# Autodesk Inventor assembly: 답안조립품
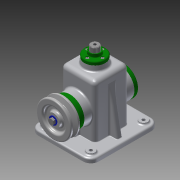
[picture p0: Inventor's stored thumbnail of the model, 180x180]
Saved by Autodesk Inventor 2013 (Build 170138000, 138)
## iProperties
Created: 2016-01
Part Number: 답안조립품
Document SubType Name: Assembly
Designer: User
Author: User
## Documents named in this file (19)
- C:\Users\User\Desktop\460126V1011\답안조립품.iam
- C:\Users\User\Desktop\460126V1011\본체.ipt
- C:\Users\User\Desktop\460126V1011\뒤커버.ipt
- C:\Users\User\Desktop\460126V1011\상부부시.ipt
- C:\Users\User\Desktop\460126V1011\앞커버.ipt
- C:\Users\User\Desktop\460126V1011\볼트 M4 x 10.ipt
- C:\Users\User\Desktop\460126V1011\볼트 M3 x 8.ipt
- C:\Users\User\Desktop\460126V1011\편심축.ipt
- C:\Users\User\Desktop\460126V1011\키 5 x 5 x 14.ipt
- C:\Users\User\Desktop\460126V1011\베어링 15 x 35 x 11.ipt
- C:\Users\User\Desktop\460126V1011\멈춤링 15 x 1.ipt
- C:\Users\User\Desktop\460126V1011\링크.ipt
- C:\Users\User\Desktop\460126V1011\멈춤링 6 x 5.ipt
- C:\Users\User\Desktop\460126V1011\슬라이드바.ipt
- C:\Users\User\Desktop\460126V1011\고정핀.ipt
- C:\Users\User\Desktop\460126V1011\오일실 15 25 7.ipt
- C:\Users\User\Desktop\460126V1011\V-벨트풀리.ipt
- C:\Users\User\Desktop\460126V1011\볼트 M6 x 12.ipt
- C:\Users\User\Desktop\460126V1011\와셔.ipt
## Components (15 placed, 5 different names)
1. 고정핀:1
2. V-벨트풀리:1 — 각도:2
3. ISO 4018 M6 x 12:1 — 각도:3
4. ISO 4762 M4 x 10:2
5. ISO 4762 M4 x 10:3
6. ISO 4762 M4 x 10:4
7. ISO 4762 M4 x 10:5
8. ISO 4762 M3 x 8:1
9. ISO 4762 M3 x 8:2
10. ISO 4762 M3 x 8:3
11. ISO 4762 M3 x 8:4
12. ISO 4762 M4 x 10:1
13. ISO 4762 M4 x 10:6
14. ISO 4762 M4 x 10:7
15. ISO 4762 M4 x 10:8
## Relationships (2: Angle 2)
- 각도:2 [Angle]: V-벨트풀리:1
- 각도:3 [Angle]: ISO 4018 M6 x 12:1
